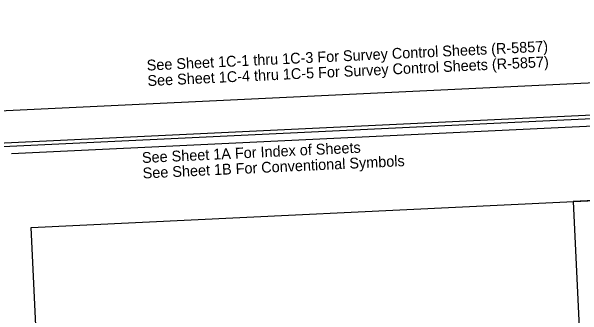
# Model space of a CAD drawing. Extents: x 2170913 to 2188101, y 74009 to 87693.
# Drawn here: x 2172605 to 2175486, y 81028 to 82562 of the extents above; entities that cross this region are included whole.
import ezdxf

# ---------------------------------------------------------------- set-up
doc = ezdxf.new("R2010")
doc.units = 0
for name, color, linetype in [('CTL Primary Horizontal and Vertical CELL', 7, 'Continuous'), ('CTL Primary Horizontal and Vertical Cogo Elevation', 7, 'Continuous'), ('CTL Primary Horizontal Cogo Comment', 7, 'Continuous'), ('CTL Primary Horizontal Cogo Number', 7, 'Continuous')]:
    doc.layers.add(name, color=color, linetype=linetype)

msp = doc.modelspace()

# ---------------------------------------------------------------- linework, layer by layer
at = {"layer": 'CTL Primary Horizontal and Vertical CELL'}
msp.add_lwpolyline([(2183118, 82562.2), (2170912.8, 81981.8), (2171291.9, 74009.3), (2183497.2, 74589.8)], close=True, dxfattribs=at)
at = {"layer": 'CTL Primary Horizontal and Vertical Cogo Elevation'}
for points in [[(2172704.4, 81472.7), (2175652.3, 81612.9), (2175771.5, 79107.1), (2172823.6, 78966.9)], [(2175652.3, 81612.9), (2175437.7, 81602.7), (2175474.6, 80826.6), (2175689.2, 80836.8)]]:
    msp.add_lwpolyline(points, close=True, dxfattribs=at)
at = {"layer": 'CTL Primary Horizontal Cogo Comment'}
msp.add_lwpolyline([(2171378.4, 74176.5), (2183456.8, 74750.8), (2183093.1, 82397.9), (2171014.8, 81823.6)], close=True, dxfattribs=at)
at = {"layer": 'CTL Primary Horizontal Cogo Number'}
for points in [[(2182931, 82371.7), (2172204.2, 81861.7)], [(2182896.4, 82333.7), (2172604.7, 81844.3)]]:
    msp.add_lwpolyline(points, dxfattribs=at)

# ---------------------------------------------------------------- texts
for s, p in [('See Sheet 1C-1 thru 1C-3 For Survey Control Sheets (R-5857)', (2173288.5, 82263.6)), ('See Sheet 1C-4 thru 1C-5 For Survey Control Sheets (R-5857)', (2173292.2, 82185.6)), ('See Sheet 1A For Index of Sheets', (2173264.4, 81797.4)), ('See Sheet 1B For Conventional Symbols', (2173268.1, 81719.4))]:
    msp.add_text(s, height=54.42, rotation=2.7227, dxfattribs=at).set_placement(p)

doc.saveas('drawing.dxf')
